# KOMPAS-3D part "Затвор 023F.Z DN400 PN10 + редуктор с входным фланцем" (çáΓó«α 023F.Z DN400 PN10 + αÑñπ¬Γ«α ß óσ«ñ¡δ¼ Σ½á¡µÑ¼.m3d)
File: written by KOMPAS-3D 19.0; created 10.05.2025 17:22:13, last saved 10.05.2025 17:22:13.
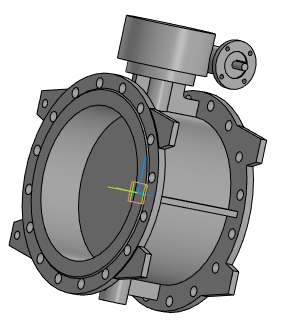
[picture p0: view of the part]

Document properties: Полное имя файла: Затвор 023F.Z DN400 PN10 + редуктор с входным фланцем.a3d

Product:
- Part/product: Затвор 023F.Z DN400 PN10 + редуктор с входным фланцем
    Масса: 187.105

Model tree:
1. Операция без истории:1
